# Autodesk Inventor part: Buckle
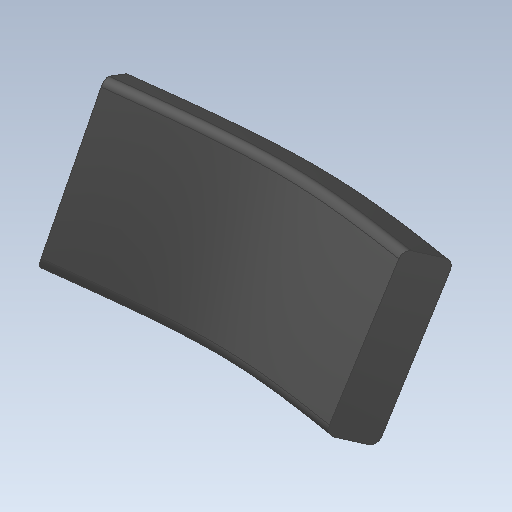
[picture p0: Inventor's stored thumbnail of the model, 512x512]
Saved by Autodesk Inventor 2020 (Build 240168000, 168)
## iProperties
Created: 2021-10
Part Number: Buckle
Material: Steel
Document SubType Name: Modeling
Designer: bruno
Density: 7.85 g/cm^3
Appearance: Par défaut
Author: bruno
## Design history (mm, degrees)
feature "Body1"
node "Solide1"
